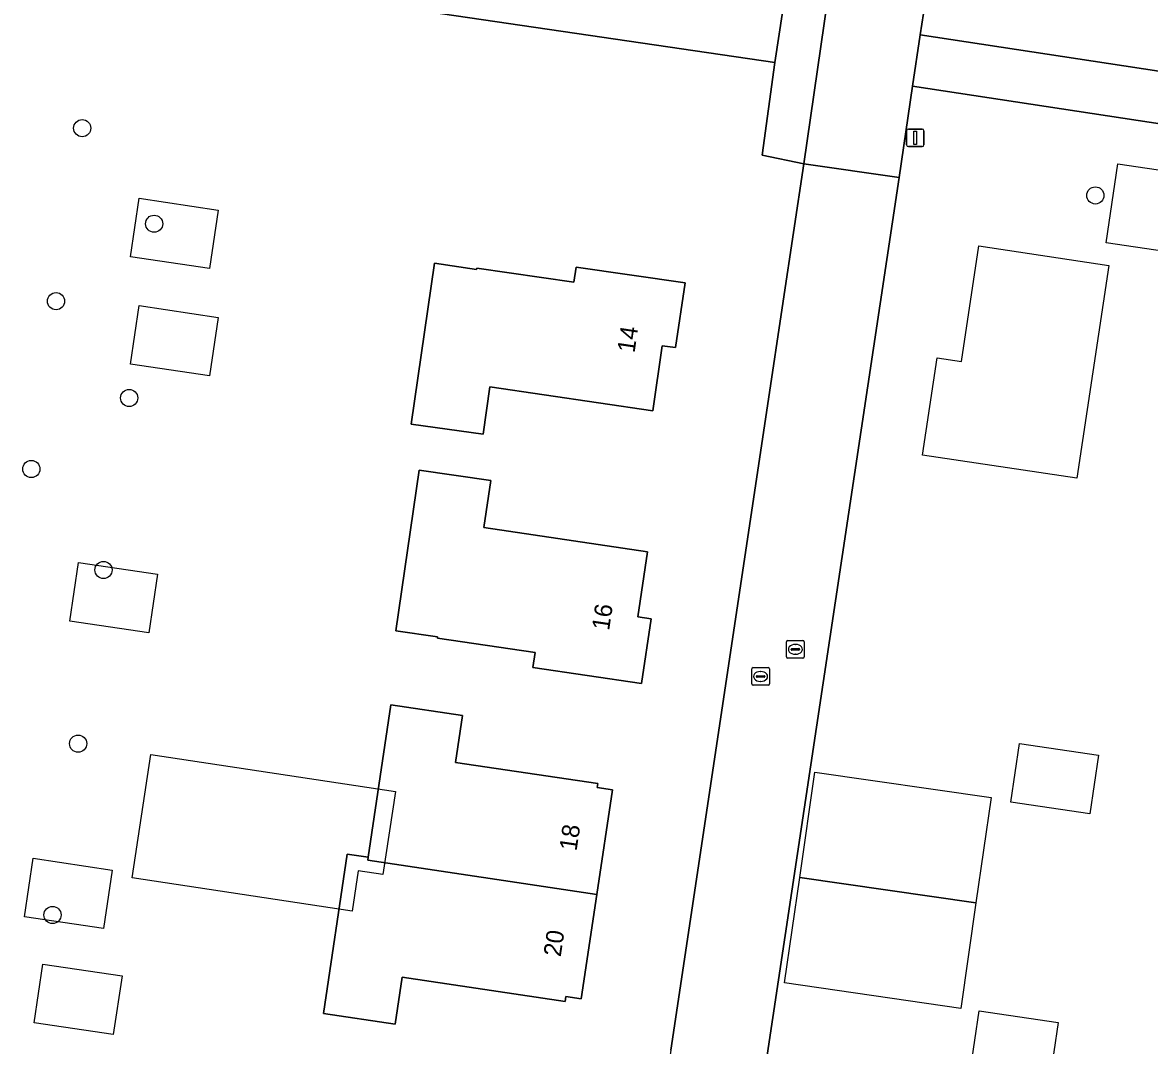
# Model space of a CAD drawing. Extents: x 164148 to 165261, y 382513 to 383432.
# Drawn here: x 164608.6 to 164672.8, y 382951.2 to 383009.5 of the extents above; entities that cross this region are included whole.
import ezdxf

# ---------------------------------------------------------------- set-up
doc = ezdxf.new("R2010")
doc.units = 0
for name, color, linetype in [('IMGEO_Boom', 7, 'Continuous'), ('IMGEO_Fietspad_gesloten', 7, 'Continuous'), ('IMGEO_Groenvoorziening', 7, 'Continuous'), ('IMGEO_Lichtmast', 7, 'Continuous'), ('IMGEO_Pand', 7, 'Continuous'), ('IMGEO_Pand_nummerreeks', 7, 'Continuous'), ('IMGEO_Pand_vergunning_verleend', 7, 'Continuous'), ('IMGEO_Rijbaan_lokaal_gesloten', 7, 'Continuous'), ('IMGEO_Rijbaan_lokaal_open', 7, 'Continuous'), ('IMGEO_Rioolput', 7, 'Continuous'), ('IMGEO_Voetpad_open', 7, 'Continuous')]:
    doc.layers.add(name, color=color, linetype=linetype)

msp = doc.modelspace()

# ---------------------------------------------------------------- linework, layer by layer
at = {"layer": 'IMGEO_Boom'}
for centre in [(164611.961, 383003.491), (164669.686, 382999.661), (164616.057, 382998.047), (164610.467, 382993.634), (164614.635, 382988.122), (164609.06, 382984.073), (164613.172, 382978.323), (164611.726, 382968.429), (164610.269, 382958.67)]:
    msp.add_circle(centre, 0.489, dxfattribs=at)
at = {"layer": 'IMGEO_Fietspad_gesloten'}
for points in [[(164606.207, 383013.843), (164611.224, 383013.148), (164651.419, 383007.225), (164651.876, 383010.215), (164622.034, 383014.618), (164609.803, 383016.423), (164601.968, 383017.579)], [(164659.708, 383008.804), (164659.275, 383005.882), (164764.64, 382989.85), (164848.685, 382977.103), (164852.653, 382976.484)], [(164853.349, 382979.402), (164849.159, 382980.044), (164765.127, 382992.769), (164659.708, 383008.804)]]:
    msp.add_lwpolyline(points, dxfattribs=at)
at = {"layer": 'IMGEO_Groenvoorziening'}
for points in [[(164792.926, 382999.883), (164668.043, 383018.43), (164669.457, 383030.808), (164666.638, 383031.227), (164664.234, 383031.584), (164664.063, 383030.618), (164662.945, 383030.79), (164662.544, 383027.92), (164660.646, 383015.127), (164663.404, 383014.779), (164663.437, 383015.117), (164665.365, 383014.843), (164665.318, 383014.554), (164668.337, 383014.189), (164668.204, 383013.184), (164669.801, 383012.974), (164669.613, 383011.378), (164668.005, 383011.557), (164667.823, 383010.303), (164660.073, 383011.264), (164659.708, 383008.804), (164765.127, 382992.769)], [(164645.496, 382950.967), (164651.008, 382987.673), (164651.902, 382993.63), (164653.078, 383001.462), (164650.705, 383001.947), (164651.419, 383007.225), (164611.224, 383013.148), (164606.207, 383013.843), (164604.952, 383005.406), (164583.055, 382858.156), (164580.335, 382839.876), (164601.872, 382836.441)], [(164852.653, 382976.484), (164848.685, 382977.103), (164764.64, 382989.85), (164659.275, 383005.882), (164658.504, 383000.69), (164650.933, 382950.305), (164641.67, 382887.255), (164640.801, 382881.34), (164637.731, 382860.442), (164636.909, 382854.849), (164636.824, 382854.453), (164636.636, 382853.576)]]:
    msp.add_lwpolyline(points, dxfattribs=at)
for points in [[(164632.029, 382995.804), (164634.426, 382995.445), (164634.437, 382995.517), (164639.974, 382994.716), (164640.107, 382995.58), (164646.304, 382994.68), (164645.761, 382990.996), (164645.008, 382991.1), (164644.462, 382987.389), (164635.187, 382988.764), (164634.798, 382986.068), (164630.707, 382986.634)], [(164631.153, 382984.005), (164635.24, 382983.412), (164634.842, 382980.742), (164644.162, 382979.358), (164643.615, 382975.658), (164644.373, 382975.545), (164643.826, 382971.849), (164637.635, 382972.77), (164637.76, 382973.617), (164632.199, 382974.437), (164632.209, 382974.508), (164629.82, 382974.864)], [(164627.059, 382962.137), (164628.257, 382961.966), (164629.544, 382970.648), (164633.618, 382970.037), (164633.225, 382967.358), (164641.329, 382966.158), (164641.296, 382965.936), (164642.165, 382965.796), (164641.274, 382959.842), (164640.383, 382953.888), (164639.517, 382954.02), (164639.476, 382953.749), (164630.197, 382955.128), (164629.782, 382952.439), (164625.707, 382953.056)]]:
    msp.add_lwpolyline(points, close=True, dxfattribs=at)
at = {"layer": 'IMGEO_Lichtmast'}
for p, q in [((164659.029, 383003.442), (164659.819, 383003.442)), ((164659.819, 383003.442), (164659.029, 383003.442)), ((164658.929, 383002.542), (164658.929, 383003.342)), ((164658.929, 383003.342), (164658.929, 383002.542)), ((164659.919, 383003.342), (164659.919, 383002.542)), ((164659.919, 383002.542), (164659.919, 383003.342)), ((164659.819, 383002.442), (164659.029, 383002.442)), ((164659.029, 383002.442), (164659.819, 383002.442))]:
    msp.add_line(p, q, dxfattribs=at)
msp.add_lwpolyline([(164659.349, 383003.317), (164659.499, 383003.317), (164659.499, 383002.567), (164659.349, 383002.567), (164659.349, 383003.317)], dxfattribs=at)
for centre, start, end in [((164659.029, 383003.342), 90, 180), ((164659.029, 383003.342), 90, 180), ((164659.819, 383003.342), 0, 90), ((164659.819, 383003.342), 360, 90), ((164659.029, 383002.542), 180, 270), ((164659.029, 383002.542), 180, 270), ((164659.819, 383002.542), 270, 0), ((164659.819, 383002.542), 270, 0)]:
    msp.add_arc(centre, 0.1, start, end, dxfattribs=at)
at = {"layer": 'IMGEO_Pand'}
for points in [[(164646.304, 382994.68), (164640.107, 382995.58), (164639.974, 382994.716), (164634.437, 382995.517), (164634.426, 382995.445), (164632.029, 382995.804), (164630.707, 382986.634), (164634.798, 382986.068), (164635.187, 382988.764), (164644.462, 382987.389), (164645.008, 382991.1), (164645.761, 382990.996)], [(164634.842, 382980.742), (164635.24, 382983.412), (164631.153, 382984.005), (164629.82, 382974.864), (164632.209, 382974.508), (164632.199, 382974.437), (164637.76, 382973.617), (164637.635, 382972.77), (164643.826, 382971.849), (164644.373, 382975.545), (164643.615, 382975.658), (164644.162, 382979.358)], [(164633.225, 382967.358), (164633.618, 382970.037), (164629.544, 382970.648), (164628.257, 382961.966), (164628.231, 382961.794), (164641.274, 382959.842), (164642.165, 382965.796), (164641.296, 382965.936), (164641.329, 382966.158)], [(164628.231, 382961.794), (164628.257, 382961.966), (164627.059, 382962.137), (164625.707, 382953.056), (164629.782, 382952.439), (164630.197, 382955.128), (164639.476, 382953.749), (164639.517, 382954.02), (164640.383, 382953.888), (164641.274, 382959.842)]]:
    msp.add_lwpolyline(points, close=True, dxfattribs=at)
at = {"layer": 'IMGEO_Pand_vergunning_verleend'}
for points in [[(164670.299, 382996.955), (164670.97, 383001.461), (164674.305, 383000.965), (164673.635, 382996.458)], [(164614.702, 382996.161), (164615.198, 382999.497), (164619.705, 382998.826), (164619.208, 382995.491)], [(164659.838, 382984.873), (164660.67, 382990.414), (164662.062, 382990.205), (164663.05, 382996.782), (164670.444, 382995.672), (164668.624, 382983.554)], [(164614.702, 382990.049), (164615.198, 382993.384), (164619.705, 382992.714), (164619.208, 382989.378)], [(164611.255, 382975.412), (164611.751, 382978.748), (164616.258, 382978.077), (164615.761, 382974.742)], [(164664.866, 382965.103), (164665.362, 382968.439), (164669.869, 382967.768), (164669.372, 382964.433)], [(164614.808, 382960.791), (164615.871, 382967.816), (164629.805, 382965.709), (164629.089, 382960.974), (164627.689, 382961.186), (164627.342, 382958.895)], [(164652.839, 382960.806), (164653.707, 382966.813), (164663.749, 382965.362), (164662.881, 382959.355)], [(164608.669, 382958.564), (164609.166, 382961.9), (164613.672, 382961.229), (164613.175, 382957.894)], [(164651.972, 382954.799), (164652.839, 382960.806), (164662.881, 382959.355), (164662.013, 382953.348)], [(164609.226, 382952.532), (164609.722, 382955.867), (164614.228, 382955.197), (164613.732, 382951.861)], [(164662.568, 382949.872), (164663.064, 382953.207), (164667.57, 382952.536), (164667.074, 382949.201)]]:
    msp.add_lwpolyline(points, close=True, dxfattribs=at)
at = {"layer": 'IMGEO_Rijbaan_lokaal_gesloten'}
msp.add_lwpolyline([(164650.933, 382950.305), (164658.504, 383000.69), (164653.078, 383001.462), (164651.902, 382993.63), (164651.008, 382987.673), (164645.496, 382950.967), (164631.941, 382858.849)], dxfattribs=at)
at = {"layer": 'IMGEO_Rijbaan_lokaal_open'}
msp.add_lwpolyline([(164662.544, 383027.92), (164662.945, 383030.79), (164664.112, 383038.673), (164665.176, 383045.892), (164659.675, 383046.714), (164658.441, 383038.338), (164657.714, 383033.452), (164653.078, 383001.462), (164658.504, 383000.69), (164659.275, 383005.882), (164659.708, 383008.804), (164660.073, 383011.264), (164660.646, 383015.127)], close=True, dxfattribs=at)
at = {"layer": 'IMGEO_Rioolput'}
for p, q in [((164652.092, 382973.375), (164652.092, 382974.227)), ((164652.167, 382974.301), (164653.019, 382974.301)), ((164652.394, 382973.844), (164652.792, 382973.844)), ((164652.58, 382974.081), (164652.605, 382974.081)), ((164653.093, 382974.227), (164653.093, 382973.375)), ((164653.019, 382973.301), (164652.167, 382973.301)), ((164652.351, 382973.795), (164652.351, 382973.807)), ((164652.789, 382973.758), (164652.391, 382973.758)), ((164652.603, 382973.521), (164652.578, 382973.521)), ((164652.835, 382973.807), (164652.835, 382973.795)), ((164650.111, 382971.832), (164650.111, 382972.684)), ((164650.186, 382972.758), (164651.038, 382972.758)), ((164651.112, 382972.684), (164651.112, 382971.832)), ((164650.37, 382972.252), (164650.37, 382972.264)), ((164650.808, 382972.215), (164650.41, 382972.215)), ((164650.413, 382972.301), (164650.811, 382972.301)), ((164650.622, 382971.978), (164650.597, 382971.978)), ((164650.599, 382972.538), (164650.624, 382972.538)), ((164650.854, 382972.264), (164650.854, 382972.252)), ((164651.038, 382971.758), (164650.186, 382971.758))]:
    msp.add_line(p, q, dxfattribs=at)
for points in [[(164652.092, 382973.375), (164652.092, 382974.227)], [(164652.167, 382974.301), (164653.019, 382974.301)], [(164653.093, 382974.227), (164653.093, 382973.375)], [(164653.019, 382973.301), (164652.167, 382973.301)], [(164650.111, 382971.832), (164650.111, 382972.684)], [(164650.186, 382972.758), (164651.038, 382972.758)], [(164651.112, 382972.684), (164651.112, 382971.832)], [(164651.038, 382971.758), (164650.186, 382971.758)]]:
    msp.add_lwpolyline(points, dxfattribs=at)
for centre, radius, start, end in [((164652.169, 382974.225), 0.0765, 91.55205, 178.44795), ((164652.169, 382974.225), 0.0765, 91.55205, 178.44795), ((164652.391, 382973.804), 0.0403, 85.87752, 175.75265), ((164652.796, 382973.806), 0.0386, 1.73085, 96.63898), ((164653.017, 382974.225), 0.0765, 1.55205, 88.44795), ((164653.017, 382974.225), 0.0765, 1.55205, 88.44795), ((164652.169, 382973.377), 0.0765, 181.55205, 268.44795), ((164652.169, 382973.377), 0.0765, 181.55205, 268.44795), ((164652.388, 382973.794), 0.0366, 178.93798, 274.71019), ((164652.792, 382973.801), 0.043, 264.86636, 352.45326), ((164653.017, 382973.377), 0.0765, 271.55205, 358.44795), ((164653.017, 382973.377), 0.0765, 271.55205, 358.44795), ((164650.188, 382972.682), 0.0765, 91.55205, 178.44795), ((164650.188, 382972.682), 0.0765, 91.55205, 178.44795), ((164651.036, 382972.682), 0.0765, 1.55205, 88.44795), ((164651.036, 382972.682), 0.0765, 1.55205, 88.44795), ((164650.41, 382972.261), 0.0403, 85.87752, 175.75265), ((164650.407, 382972.251), 0.0366, 178.93798, 274.71019), ((164650.811, 382972.258), 0.043, 264.86636, 352.45326), ((164650.815, 382972.263), 0.0386, 1.73085, 96.63898), ((164650.188, 382971.834), 0.0765, 181.55205, 268.44795), ((164650.188, 382971.834), 0.0765, 181.55205, 268.44795), ((164651.036, 382971.834), 0.0765, 271.55205, 358.44795), ((164651.036, 382971.834), 0.0765, 271.55205, 358.44795)]:
    msp.add_arc(centre, radius, start, end, dxfattribs=at)
for centre, major_axis, ratio, start_param, end_param in [((164652.579, 382973.801), (-0.387, 0.002), 0.722429, 4.712389, 7.853982), ((164652.604, 382973.801), (-0.39, 0.002), 0.717154, 1.570796, 4.712389), ((164650.598, 382972.258), (-0.387, 0.002), 0.722429, 4.712389, 7.853982), ((164650.623, 382972.258), (-0.39, 0.002), 0.717154, 1.570796, 4.712389)]:
    msp.add_ellipse(centre, major_axis=major_axis, ratio=ratio, start_param=start_param, end_param=end_param, dxfattribs=at)
at = {"layer": 'IMGEO_Voetpad_open'}
msp.add_lwpolyline([(164672.613, 383150.649), (164653.403, 383020.558), (164653.018, 383017.951), (164651.876, 383010.215), (164651.419, 383007.225), (164650.705, 383001.947), (164653.078, 383001.462), (164657.714, 383033.452), (164656.509, 383033.621), (164657.237, 383038.501), (164658.441, 383038.338), (164659.675, 383046.714), (164660.382, 383051.508), (164663.299, 383071.06), (164663.405, 383071.768), (164663.423, 383071.905), (164662.198, 383072.123), (164662.932, 383077.035), (164664.173, 383076.85), (164666.161, 383090.76)], dxfattribs=at)

# ---------------------------------------------------------------- texts
at = {"layer": 'IMGEO_Pand_nummerreeks'}
for s, rotation, p in [('14', 81.6293, (164643.426, 382990.658)), ('16', 81.58919, (164641.978, 382974.841)), ('18', 81.49179, (164640.122, 382962.278)), ('20', 81.49179, (164639.22, 382956.254))]:
    msp.add_text(s, height=1, rotation=rotation, dxfattribs=at).set_placement(p)

doc.saveas('drawing.dxf')
